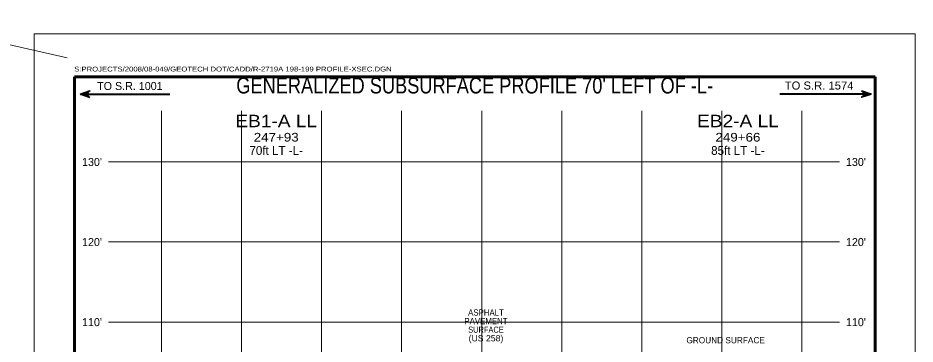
# Model space of a CAD drawing. Extents: x -76 to 974, y -1080 to -735.
# Drawn here: x 105.5 to 217.5, y -924.8 to -884.1 of the extents above; entities that cross this region are included whole.
import ezdxf
from ezdxf.enums import TextEntityAlignment as Align

# ---------------------------------------------------------------- set-up
doc = ezdxf.new("R2010")
doc.units = 0
doc.header["$LTSCALE"] = 0.36
for name, color, linetype, lineweight in [('10', 7, 'Continuous', 35), ('27', 7, 'Continuous', 40), ('63', 7, 'Continuous', 35), ('7', 7, 'Continuous', 13)]:
    doc.layers.add(name, color=color, linetype=linetype, lineweight=lineweight)

msp = doc.modelspace()

# ---------------------------------------------------------------- hatches: boundary and pattern name
at = {"layer": '10'}
for points in [[(114.4677, -894.0323), (113.2677, -893.6323), (114.4677, -893.2323), (114.0677, -893.6323)], [(210.8273, -893.2277), (212.0273, -893.6277), (210.8273, -894.0277), (211.2273, -893.6277)]]:
    msp.add_hatch(color=256, dxfattribs=at).paths.add_polyline_path(points)

# ---------------------------------------------------------------- linework, layer by layer
for points in [[(114.4677, -894.0323), (113.2677, -893.6323), (114.4677, -893.2323), (114.0677, -893.6323)], [(210.8273, -893.2277), (212.0273, -893.6277), (210.8273, -894.0277), (211.2273, -893.6277)]]:
    msp.add_lwpolyline(points, close=True, dxfattribs=at)
at = {"layer": '27', "lineweight": 13}
msp.add_line((111.598, -889.0898), (89.408, -884.1181), dxfattribs=at)
at = {"layer": '27'}
for p, q in [((113.2678, -893.6322), (124.4424, -893.6322)), ((212.0273, -893.6276), (200.6055, -893.6313))]:
    msp.add_line(p, q, dxfattribs=at)
at = {"layer": '63', "lineweight": 13}
for p, q in [((107.515, -886.1123), (107.515, -1056.1123)), ((107.515, -886.1123), (217.515, -886.1123)), ((217.515, -1056.1123), (217.515, -886.1123))]:
    msp.add_line(p, q, dxfattribs=at)
at = {"layer": '63', "lineweight": 60}
for p, q in [((112.515, -1052.1123), (112.515, -891.4595)), ((212.515, -891.4595), (112.515, -891.4595)), ((212.515, -891.4595), (212.515, -1052.1123))]:
    msp.add_line(p, q, dxfattribs=at)
at = {"layer": '7'}
for p, q in [((123.3912, -1033.3123), (123.3912, -895.7205)), ((133.3912, -1033.3123), (133.3912, -895.7205)), ((143.3912, -933.9727), (143.3912, -895.7205)), ((153.3912, -1042.0988), (153.3912, -895.7205)), ((163.3912, -1042.0988), (163.3912, -895.7205)), ((173.3912, -1042.0988), (173.3912, -895.7205)), ((183.3912, -1042.0988), (183.3912, -895.7205)), ((193.3912, -1042.0988), (193.3912, -895.7205)), ((203.3912, -1042.0988), (203.3912, -895.7205)), ((116.7824, -902.09), (208.0761, -902.09)), ((116.7824, -912.09), (208.0761, -912.09)), ((116.7824, -922.09), (208.0761, -922.09))]:
    msp.add_line(p, q, dxfattribs=at)

# ---------------------------------------------------------------- texts
at = {"layer": '27'}
for s, height, p in [('TO S.R. 1001', 1, (119.4519, -893.1141)), ('70ft LT -L-', 1.085, (137.7262, -901.2115)), ('85ft LT -L-', 1.085, (195.3933, -901.2115)), ('GROUND SURFACE', 0.7717, (193.8582, -924.74))]:
    msp.add_text(s, height=height, dxfattribs=at).set_placement(p, align=Align.CENTER)
for s, height, width, p in [('TO S.R. 1574', 1, 1.05, (205.534, -893.0575)), ('EB1-A LL', 1.55, 1.15, (137.7259, -897.7581)), ('EB2-A LL', 1.55, 1.15, (195.3929, -897.7581)), ('247+93', 1.085, 1.15, (137.7267, -899.5545)), ('249+66', 1.085, 1.15, (195.3939, -899.5545)), ('ASPHALT', 0.7718, 0.95, (163.9258, -921.2798)), ('PAVEMENT', 0.7718, 0.95, (163.9258, -922.3516)), ('SURFACE', 0.7718, 0.9, (163.9258, -923.4234)), ('(US 258)', 0.7718, 1.05, (163.9258, -924.4951))]:
    msp.add_text(s, height=height, dxfattribs=dict(at, width=width)).set_placement(p, align=Align.CENTER)
at = {"layer": '63', "width": 1.2}
msp.add_text('S:PROJECTS/2008/08-049/GEOTECH DOT/CADD/R-2719A 198-199 PROFILE-XSEC.DGN', height=0.6, dxfattribs=at).set_placement((112.4986, -890.8007))
at = {"layer": '63', "width": 0.85}
msp.add_text("GENERALIZED SUBSURFACE PROFILE 70' LEFT OF -L-", height=2, dxfattribs=at).set_placement((162.515, -893.5476), align=Align.CENTER)
at = {"layer": '63'}
for s, p in [("130'", (114.7209, -902.6008)), ("130'", (210.1293, -902.6008)), ("120'", (114.7209, -912.6008)), ("120'", (210.1293, -912.6008)), ("110'", (114.721, -922.6008)), ("110'", (210.1294, -922.6008))]:
    msp.add_text(s, height=1, dxfattribs=at).set_placement(p, align=Align.CENTER)

doc.saveas('drawing.dxf')
